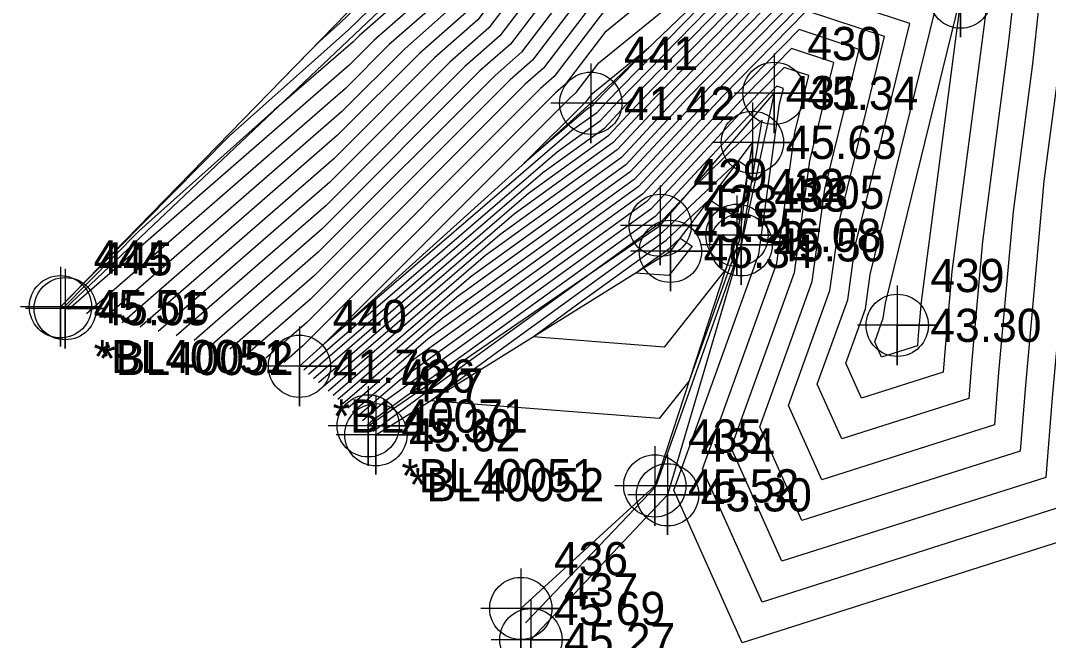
# Model space of a CAD drawing. Extents: x 2090860 to 2091277, y 159470 to 160080.
# Drawn here: x 2090967.2 to 2091044.6, y 159683.4 to 159730.1 of the extents above; entities that cross this region are included whole.
import ezdxf

# ---------------------------------------------------------------- set-up
doc = ezdxf.new("R2010")
doc.units = 0
for name, color, linetype in [('DTM Contours Major', 7, 'Continuous'), ('DTM Contours Minor', 7, 'Continuous'), ('Exist DTM Breakline', 7, 'Continuous'), ('Exist DTM Breakline Cogo Comment', 7, 'Continuous'), ('Exist DTM Breakline Cogo Elevation', 7, 'Continuous'), ('Exist DTM Breakline Cogo Number', 7, 'Continuous'), ('Exist DTM Breakline Cogo Point CELL', 7, 'Continuous'), ('Exist DTM Breakline Underwater', 7, 'Continuous'), ('Exist DTM Breakline Underwater Cogo Comment', 7, 'Continuous'), ('Exist DTM Breakline Underwater Cogo Elevation', 7, 'Continuous'), ('Exist DTM Breakline Underwater Cogo Number', 7, 'Continuous'), ('Exist DTM Breakline Underwater Cogo Point CELL', 7, 'Continuous'), ('Exist DTM Regular Point Underwater CELL', 7, 'Continuous'), ('Exist DTM Regular Point Underwater Cogo Elevation', 7, 'Continuous'), ('Exist DTM Regular Point Underwater Cogo Number', 7, 'Continuous')]:
    doc.layers.add(name, color=color, linetype=linetype)

msp = doc.modelspace()

# ---------------------------------------------------------------- linework, layer by layer
at = {"layer": 'DTM Contours Major'}
for points in [[(2091091.582, 159898.637), (2091075.464, 159895.754), (2091071.361, 159891.649), (2091065.515, 159864.769), (2091059.162, 159855.905), (2091062.527, 159845.344), (2091062.382, 159844.528), (2091071.24, 159827.424), (2091068.468, 159817.052), (2091062.553, 159811.484), (2091060.259, 159801.479), (2091046.876, 159791.945), (2091037.586, 159782.801), (2091031.987, 159764.384), (2091026.688, 159760.214), (2091021.294, 159752.688), (2091014.874, 159747.469), (2091001.671, 159730.125), (2090998.416, 159727.263), (2090990.823, 159719.668), (2090976.25, 159706.989)], [(2091099.517, 159890.851), (2091094.379, 159889.932), (2091085.334, 159880.882), (2091082.516, 159867.927), (2091070.303, 159850.886), (2091072.441, 159844.175), (2091072.201, 159842.82), (2091077.78, 159832.047), (2091073.12, 159814.614), (2091069.924, 159811.606), (2091065.116, 159790.633), (2091059.844, 159786.877), (2091043.696, 159770.983), (2091041.123, 159762.521), (2091029.056, 159753.026), (2091026.145, 159748.964), (2091013.055, 159738.321), (2091004.963, 159727.692), (2091002.968, 159725.938), (2090989.66, 159712.626), (2090981.654, 159705.661)], [(2091031.476, 159794.619), (2091026.533, 159778.36), (2091022.159, 159773.459), (2091024.771, 159765.861), (2091016.801, 159756.497), (2091016.608, 159756.29), (2091015.762, 159755.383), (2091014.915, 159754.282), (2090998.378, 159732.557), (2090993.863, 159728.588), (2090991.986, 159726.71), (2090970.846, 159708.318)], [(2091087.501, 159783.333), (2091087.769, 159779.288), (2091084.366, 159766.629), (2091076.14, 159769.26), (2091074.973, 159768.174), (2091066.061, 159756.411), (2091053.904, 159745.604), (2091047.888, 159738.533), (2091043.463, 159732.701), (2091041.966, 159731.422), (2091041.639, 159728.479), (2091039.685, 159713.437), (2091038.871, 159704.507), (2091038.64, 159701.617), (2091029.076, 159698.576), (2091027.234, 159702.684), (2091029.528, 159709.044), (2091030.086, 159713.086), (2091034.203, 159729.856), (2091026.977, 159732.23), (2091019.254, 159724.332), (2091013.442, 159718.102), (2090999.017, 159707.674), (2090991.506, 159701.21)], [(2091075.953, 159781.891), (2091074.613, 159776.904), (2091071.372, 159777.941), (2091070.912, 159777.513), (2091056.779, 159758.858), (2091051.193, 159753.892), (2091040.5, 159741.323), (2091036.181, 159735.631), (2091029.212, 159737.921), (2091015.739, 159724.142), (2091012.177, 159720.324), (2091003.337, 159713.933), (2090990.035, 159702.486)], [(2090988.564, 159703.762), (2091007.657, 159720.192), (2091010.912, 159722.546), (2091012.224, 159723.952), (2091031.448, 159743.611), (2091032.475, 159743.273), (2091033.111, 159744.112), (2091040.966, 159753.345), (2091031.424, 159745.838), (2091030.995, 159745.239), (2091011.235, 159729.174), (2091008.255, 159725.259), (2091007.521, 159724.613), (2090988.497, 159705.583), (2090987.059, 159704.332)], [(2091046.379, 159693.703), (2091023.075, 159686.293), (2091018.587, 159696.304), (2091024.177, 159711.802), (2091025.536, 159721.65), (2091026.587, 159725.933), (2091024.742, 159726.54), (2091022.769, 159724.523), (2091014.707, 159715.88), (2090994.697, 159701.415), (2090992.977, 159699.935)], [(2091008.827, 159708.454), (2091015.844, 159713.532), (2091019.111, 159716.597), (2091021.386, 159715.096), (2091021.229, 159713.807), (2091020.35, 159711.347), (2091015.693, 159705.481), (2091005.827, 159706.251), (2091008.827, 159708.454)]]:
    msp.add_lwpolyline(points, dxfattribs=at)
at = {"layer": 'DTM Contours Minor'}
for points in [[(2091085.63, 159904.476), (2091061.277, 159900.12), (2091060.882, 159899.725), (2091052.763, 159862.4), (2091050.806, 159859.669), (2091055.091, 159846.22), (2091055.018, 159845.809), (2091066.336, 159823.957), (2091064.979, 159818.88), (2091057.025, 159811.393), (2091056.616, 159809.613), (2091037.15, 159795.745), (2091033.004, 159791.665), (2091025.134, 159765.782), (2091024.911, 159765.606), (2091017.656, 159755.482), (2091016.238, 159754.329), (2090999.201, 159731.949), (2090995.001, 159728.257), (2090991.695, 159724.95), (2090972.197, 159707.986)], [(2091087.614, 159902.53), (2091066.006, 159898.665), (2091064.375, 159897.033), (2091057.014, 159863.189), (2091053.591, 159858.414), (2091057.57, 159845.928), (2091057.473, 159845.382), (2091067.971, 159825.113), (2091066.142, 159818.271), (2091058.867, 159811.424), (2091057.831, 159806.902), (2091040.392, 159794.478), (2091034.531, 159788.71), (2091027.419, 159765.316), (2091025.503, 159763.809), (2091018.868, 159754.551), (2091015.783, 159752.042), (2091000.024, 159731.341), (2090996.139, 159727.925), (2090991.404, 159723.189), (2090973.548, 159707.654)], [(2091089.598, 159900.583), (2091070.735, 159897.209), (2091067.868, 159894.341), (2091061.264, 159863.979), (2091056.377, 159857.16), (2091060.048, 159845.636), (2091059.927, 159844.955), (2091069.606, 159826.269), (2091067.305, 159817.661), (2091060.71, 159811.454), (2091059.045, 159804.19), (2091043.634, 159793.212), (2091036.059, 159785.755), (2091029.703, 159764.85), (2091026.095, 159762.012), (2091020.081, 159753.62), (2091015.328, 159749.755), (2091000.847, 159730.733), (2090997.277, 159727.594), (2090991.114, 159721.429), (2090974.899, 159707.322)], [(2091093.566, 159896.69), (2091080.192, 159894.298), (2091074.854, 159888.957), (2091069.765, 159865.558), (2091061.947, 159854.65), (2091065.005, 159845.052), (2091064.837, 159844.101), (2091072.875, 159828.58), (2091069.631, 159816.443), (2091064.396, 159811.515), (2091061.473, 159798.767), (2091050.118, 159790.678), (2091039.113, 159779.846), (2091034.271, 159763.918), (2091027.28, 159758.417), (2091022.507, 159751.757), (2091014.419, 159745.182), (2091002.494, 159729.516), (2090999.554, 159726.932), (2090990.532, 159717.907), (2090977.601, 159706.657)], [(2091095.549, 159894.744), (2091084.921, 159892.843), (2091078.348, 159886.266), (2091074.015, 159866.348), (2091064.733, 159853.396), (2091067.484, 159844.76), (2091067.291, 159843.674), (2091074.51, 159829.736), (2091070.794, 159815.833), (2091066.238, 159811.545), (2091062.688, 159796.056), (2091053.36, 159789.411), (2091040.641, 159776.892), (2091036.555, 159763.452), (2091027.872, 159756.62), (2091023.719, 159750.826), (2091013.964, 159742.895), (2091003.317, 159728.908), (2091000.692, 159726.601), (2090990.241, 159716.147), (2090978.952, 159706.325)], [(2091097.533, 159892.797), (2091089.65, 159891.387), (2091081.841, 159883.574), (2091078.266, 159867.137), (2091067.518, 159852.141), (2091069.963, 159844.468), (2091069.746, 159843.247), (2091076.145, 159830.892), (2091071.957, 159815.224), (2091068.081, 159811.575), (2091063.902, 159793.344), (2091056.602, 159788.144), (2091042.168, 159773.937), (2091038.839, 159762.987), (2091028.464, 159754.823), (2091024.932, 159749.895), (2091013.509, 159740.608), (2091004.14, 159728.3), (2091001.83, 159726.269), (2090989.951, 159714.386), (2090980.303, 159705.993)], [(2091101.501, 159888.904), (2091099.107, 159888.476), (2091088.827, 159878.19), (2091086.766, 159868.717), (2091073.088, 159849.632), (2091074.92, 159843.883), (2091074.655, 159842.393), (2091079.415, 159833.203), (2091074.283, 159814.005), (2091071.767, 159811.636), (2091066.33, 159787.921), (2091063.086, 159785.61), (2091045.223, 159768.028), (2091043.407, 159762.055), (2091029.648, 159751.229), (2091027.357, 159748.032), (2091012.6, 159736.034), (2091005.786, 159727.084), (2091004.106, 159725.607), (2090989.369, 159710.865), (2090983.005, 159705.329)], [(2091017.431, 159786.838), (2091024.63, 159765.903), (2091019.161, 159759.478), (2091016.387, 159756.502), (2091004.237, 159743.466), (2090996.79, 159733.786), (2090993.454, 159730.838), (2090991.938, 159729.378), (2090982.952, 159721.358), (2090970.247, 159708.52)], [(2091066.328, 159784.343), (2091046.751, 159765.073), (2091045.691, 159761.589), (2091030.24, 159749.432), (2091028.57, 159747.101), (2091012.145, 159733.748), (2091006.609, 159726.476), (2091005.244, 159725.276), (2090989.078, 159709.104), (2090984.356, 159704.996)], [(2091090.414, 159783.295), (2091090.724, 159778.637), (2091086.804, 159764.06), (2091077.332, 159767.09), (2091075.988, 159765.839), (2091068.382, 159755.8), (2091054.582, 159743.532), (2091049.736, 159737.835), (2091046.17, 159733.137), (2091043.929, 159731.221), (2091043.438, 159726.812), (2091041.995, 159715.704), (2091040.889, 159703.567), (2091040.574, 159699.638), (2091027.576, 159695.505), (2091025.072, 159701.089), (2091028.191, 159709.733), (2091028.948, 159715.227), (2091032.299, 159728.875), (2091026.418, 159730.808), (2091020.133, 159724.38), (2091013.758, 159717.546), (2090997.937, 159706.109), (2090991.874, 159700.892)], [(2091093.328, 159783.257), (2091093.678, 159777.986), (2091089.243, 159761.491), (2091078.524, 159764.92), (2091077.003, 159763.504), (2091070.702, 159755.188), (2091055.259, 159741.46), (2091051.583, 159737.138), (2091048.878, 159733.573), (2091045.891, 159731.02), (2091045.237, 159725.146), (2091044.305, 159717.971), (2091042.908, 159702.627), (2091042.509, 159697.66), (2091026.075, 159692.434), (2091022.911, 159699.494), (2091026.853, 159710.423), (2091027.811, 159717.368), (2091030.395, 159727.895), (2091025.859, 159729.385), (2091021.012, 159724.428), (2091014.074, 159716.991), (2090996.857, 159704.544), (2090992.242, 159700.573)], [(2091096.241, 159783.219), (2091096.632, 159777.335), (2091091.681, 159758.923), (2091079.716, 159762.75), (2091078.018, 159761.17), (2091073.023, 159754.576), (2091055.937, 159739.388), (2091053.43, 159736.44), (2091051.585, 159734.01), (2091047.854, 159730.819), (2091047.036, 159723.479), (2091046.615, 159720.238), (2091044.926, 159701.687), (2091044.444, 159695.681), (2091024.575, 159689.363), (2091020.749, 159697.899), (2091025.515, 159711.112), (2091026.673, 159719.509), (2091028.491, 159726.914), (2091025.301, 159727.962), (2091021.891, 159724.475), (2091014.39, 159716.435), (2090995.777, 159702.98), (2090992.609, 159700.254)], [(2091019.078, 159782.234), (2091024.701, 159765.882), (2091017.981, 159757.987), (2091016.497, 159756.396), (2091010, 159749.425), (2091003.491, 159740.964), (2090997.555, 159733.165), (2090992.725, 159728.919), (2090992.277, 159728.471), (2090986.347, 159723.312), (2090976.167, 159714.226), (2090970.443, 159708.442)], [(2090987.359, 159726.086), (2090989.738, 159728.489), (2090991.312, 159729.894), (2090995.036, 159733.482), (2090996.1, 159734.422), (2090998.474, 159737.508), (2091016.276, 159756.608), (2091020.341, 159760.969), (2091024.559, 159765.924), (2091019.007, 159782.07)], [(2090989.3, 159703.124), (2091005.497, 159717.062), (2091011.545, 159721.435), (2091013.982, 159724.047), (2091030.33, 159740.766), (2091034.328, 159739.452), (2091036.806, 159742.718), (2091049.838, 159758.036), (2091052.138, 159760.081), (2091068.882, 159782.182)], [(2091078.907, 159781.24), (2091077.051, 159774.335), (2091072.564, 159775.771), (2091071.927, 159775.178), (2091059.099, 159758.246), (2091051.871, 159751.82), (2091042.347, 159740.625), (2091037.107, 159733.72), (2091028.653, 159736.498), (2091016.618, 159724.19), (2091012.493, 159719.768), (2091002.257, 159712.368), (2090990.403, 159702.167)], [(2091081.861, 159780.589), (2091079.489, 159771.767), (2091073.756, 159773.601), (2091072.942, 159772.843), (2091061.42, 159757.634), (2091052.549, 159749.748), (2091044.194, 159739.928), (2091038.048, 159731.828), (2091038.042, 159731.823), (2091038.04, 159731.812), (2091035.064, 159708.902), (2091034.835, 159706.388), (2091034.77, 159705.574), (2091032.077, 159704.717), (2091031.558, 159705.874), (2091032.204, 159707.665), (2091032.361, 159708.804), (2091038.011, 159731.817), (2091028.095, 159735.075), (2091017.497, 159724.237), (2091012.809, 159719.213), (2091001.177, 159710.803), (2090990.771, 159701.848)], [(2091069.897, 159779.847), (2091054.458, 159759.469), (2091050.515, 159755.964), (2091038.653, 159742.02), (2091035.254, 159737.542), (2091029.771, 159739.343), (2091014.861, 159724.095), (2091011.861, 159720.879), (2091004.417, 159715.498), (2090989.667, 159702.805)], [(2091084.815, 159779.939), (2091081.928, 159769.198), (2091074.948, 159771.43), (2091073.958, 159770.509), (2091063.74, 159757.023), (2091053.226, 159747.676), (2091046.041, 159739.23), (2091040.755, 159732.265), (2091040.004, 159731.622), (2091039.84, 159730.145), (2091037.374, 159711.17), (2091036.853, 159705.448), (2091036.705, 159703.595), (2091030.576, 159701.647), (2091029.396, 159704.279), (2091030.866, 159708.355), (2091031.224, 159710.945), (2091036.107, 159730.837), (2091027.536, 159733.653), (2091018.376, 159724.285), (2091013.126, 159718.657), (2091000.097, 159709.239), (2090991.138, 159701.529)], [(2090988.932, 159703.443), (2091006.577, 159718.627), (2091011.229, 159721.99), (2091013.103, 159723.999), (2091030.889, 159742.188), (2091033.401, 159741.363), (2091034.959, 159743.415), (2091049.16, 159760.108), (2091049.817, 159760.692), (2091058.581, 159772.26), (2091048.278, 159762.119), (2091047.975, 159761.123), (2091030.832, 159747.635), (2091029.783, 159746.17), (2091011.69, 159731.461), (2091007.432, 159725.867), (2091006.383, 159724.945), (2090988.787, 159707.344), (2090985.707, 159704.664)], [(2090990.11, 159705.727), (2091008.659, 159724.282), (2091009.079, 159724.651), (2091010.781, 159726.887), (2091027.762, 159740.693), (2091011.346, 159723.904), (2091010.596, 159723.101), (2091008.736, 159721.757), (2090990.11, 159705.727)], [(2091005.174, 159719.326), (2091009.797, 159723.951), (2091009.902, 159724.043), (2091010.326, 159724.6), (2091014.559, 159728.041), (2091010.467, 159723.857), (2091010.28, 159723.657), (2091009.816, 159723.322), (2091005.174, 159719.326)], [(2091048.314, 159691.724), (2091021.574, 159683.222), (2091016.425, 159694.709), (2091022.839, 159712.491), (2091024.398, 159723.792), (2091024.683, 159724.953), (2091024.183, 159725.117), (2091023.648, 159724.57), (2091015.023, 159715.324), (2090993.617, 159699.85), (2090993.345, 159699.616)], [(2091005.255, 159684.74), (2091010.318, 159689.997), (2091015.068, 159694.991), (2091021.468, 159713.087), (2091021.501, 159713.18), (2091021.512, 159713.255), (2091023.088, 159722.575), (2091017.569, 159717.159), (2091015.339, 159714.769), (2091010.853, 159711.526), (2090997.865, 159702.125), (2090993.785, 159699.13)], [(2091003.346, 159705.29), (2091015.599, 159714.158), (2091021.305, 159719.509), (2091022.038, 159719.025), (2091021.363, 159713.494), (2091017.592, 159702.941), (2091015.336, 159700.099), (2090998.106, 159701.442), (2091003.346, 159705.29)], [(2091014.308, 159711.618), (2091016.089, 159712.907), (2091016.918, 159713.684), (2091017.818, 159713.09), (2091016.051, 159710.864), (2091013.547, 159711.059), (2091014.308, 159711.618)]]:
    msp.add_lwpolyline(points, dxfattribs=at)
at = {"layer": 'Exist DTM Breakline'}
for points in [[(2090970.238, 159708.524), (2090995.777, 159734.72), (2091024.32, 159765.995), (2091015.838, 159787.603), (2090997.039, 159829.071)], [(2090970.603, 159708.378), (2090997.094, 159733.506), (2091024.833, 159765.843), (2091016.946, 159788.306), (2090998.355, 159829.241)], [(2090993.414, 159699.556), (2091015.406, 159714.651), (2091023.975, 159724.588), (2091021.496, 159713.183), (2091015.958, 159694.364), (2091005.671, 159683.46)], [(2090993.999, 159698.884), (2091016.172, 159712.694), (2091022.349, 159720.896), (2091021.188, 159713.902), (2091015, 159695.039), (2091004.908, 159685.809)]]:
    msp.add_lwpolyline(points, dxfattribs=at)
at = {"layer": 'Exist DTM Breakline Cogo Point CELL'}
for points in [[(2091023.975, 159727.588), (2091023.975, 159721.588), (2091023.975, 159724.588), (2091026.975, 159724.588), (2091020.975, 159724.588)], [(2091022.349, 159723.896), (2091022.349, 159717.896), (2091022.349, 159720.896), (2091025.349, 159720.896), (2091019.349, 159720.896)], [(2091015.406, 159717.651), (2091015.406, 159711.651), (2091015.406, 159714.651), (2091018.406, 159714.651), (2091012.406, 159714.651)], [(2091021.188, 159716.902), (2091021.188, 159710.902), (2091021.188, 159713.902), (2091024.188, 159713.902), (2091018.188, 159713.902)], [(2091021.496, 159716.183), (2091021.496, 159710.183), (2091021.496, 159713.183), (2091024.496, 159713.183), (2091018.496, 159713.183)], [(2091016.172, 159715.694), (2091016.172, 159709.694), (2091016.172, 159712.694), (2091019.172, 159712.694), (2091013.172, 159712.694)], [(2090970.238, 159711.524), (2090970.238, 159705.524), (2090970.238, 159708.524), (2090973.238, 159708.524), (2090967.238, 159708.524)], [(2090970.603, 159711.378), (2090970.603, 159705.378), (2090970.603, 159708.378), (2090973.603, 159708.378), (2090967.603, 159708.378)], [(2090993.414, 159702.556), (2090993.414, 159696.556), (2090993.414, 159699.556), (2090996.414, 159699.556), (2090990.414, 159699.556)], [(2090993.999, 159701.884), (2090993.999, 159695.884), (2090993.999, 159698.884), (2090996.999, 159698.884), (2090990.999, 159698.884)], [(2091015, 159698.039), (2091015, 159692.039), (2091015, 159695.039), (2091018, 159695.039), (2091012, 159695.039)], [(2091015.958, 159697.364), (2091015.958, 159691.364), (2091015.958, 159694.364), (2091018.958, 159694.364), (2091012.958, 159694.364)], [(2091004.908, 159688.809), (2091004.908, 159682.809), (2091004.908, 159685.809), (2091007.908, 159685.809), (2091001.908, 159685.809)], [(2091005.671, 159686.46), (2091005.671, 159680.46), (2091005.671, 159683.46), (2091008.671, 159683.46), (2091002.671, 159683.46)]]:
    msp.add_lwpolyline(points, dxfattribs=at)
for centre in [(2091023.975, 159724.588), (2091022.349, 159720.896), (2091015.406, 159714.651), (2091021.188, 159713.902), (2091021.496, 159713.183), (2091016.172, 159712.694), (2090970.238, 159708.524), (2090970.603, 159708.378), (2090993.414, 159699.556), (2090993.999, 159698.884), (2091015, 159695.039), (2091015.958, 159694.364), (2091004.908, 159685.809), (2091005.671, 159683.46)]:
    msp.add_circle(centre, 2.344, dxfattribs=at)
at = {"layer": 'Exist DTM Breakline Underwater'}
msp.add_lwpolyline([(2090988.242, 159704.041), (2091010.175, 159723.841), (2091048.889, 159760.937), (2091068.273, 159783.583), (2091089.722, 159842.139), (2091103.231, 159887.207)], dxfattribs=at)
at = {"layer": 'Exist DTM Breakline Underwater Cogo Point CELL'}
for points in [[(2091010.175, 159726.841), (2091010.175, 159720.841), (2091010.175, 159723.841), (2091013.175, 159723.841), (2091007.175, 159723.841)], [(2090988.242, 159707.041), (2090988.242, 159701.041), (2090988.242, 159704.041), (2090991.242, 159704.041), (2090985.242, 159704.041)]]:
    msp.add_lwpolyline(points, dxfattribs=at)
for centre in [(2091010.175, 159723.841), (2090988.242, 159704.041)]:
    msp.add_circle(centre, 2.344, dxfattribs=at)
at = {"layer": 'Exist DTM Regular Point Underwater CELL'}
for points in [[(2091038.026, 159734.825), (2091038.026, 159728.825), (2091038.026, 159731.825), (2091041.026, 159731.825), (2091035.026, 159731.825)], [(2091033.253, 159710.125), (2091033.253, 159704.125), (2091033.253, 159707.125), (2091036.253, 159707.125), (2091030.253, 159707.125)]]:
    msp.add_lwpolyline(points, dxfattribs=at)
for centre in [(2091038.026, 159731.825), (2091033.253, 159707.125)]:
    msp.add_circle(centre, 2.344, dxfattribs=at)

# ---------------------------------------------------------------- texts
at = {"layer": 'Exist DTM Breakline Cogo Comment'}
for s, p in [('4005', (2091024.849, 159715.896)), ('*BL40051', (2090972.738, 159703.524)), ('*BL40052', (2090973.103, 159703.378)), ('*BL40051', (2090995.914, 159694.556)), ('*BL40052', (2090996.499, 159693.884))]:
    msp.add_text(s, height=2.5, dxfattribs=at).set_placement(p)
at = {"layer": 'Exist DTM Breakline Cogo Elevation'}
for s, p in [('45.34', (2091026.475, 159723.338)), ('45.63', (2091024.849, 159719.646)), ('45.55', (2091017.906, 159713.401)), ('46.08', (2091023.688, 159712.652)), ('46.34', (2091018.672, 159711.444)), ('45.50', (2091023.996, 159711.933)), ('45.51', (2090972.738, 159707.274)), ('45.05', (2090973.103, 159707.128)), ('45.30', (2090995.914, 159698.306)), ('45.62', (2090996.499, 159697.634)), ('45.52', (2091017.5, 159693.789)), ('45.30', (2091018.458, 159693.114)), ('45.69', (2091007.408, 159684.559)), ('45.27', (2091008.171, 159682.21))]:
    msp.add_text(s, height=2.5, dxfattribs=at).set_placement(p)
at = {"layer": 'Exist DTM Breakline Cogo Number'}
for s, p in [('430', (2091026.475, 159727.088)), ('431', (2091024.849, 159723.396)), ('429', (2091017.906, 159717.151)), ('432', (2091023.688, 159716.402)), ('428', (2091018.672, 159715.194)), ('433', (2091023.996, 159715.683)), ('444', (2090972.738, 159711.024)), ('445', (2090973.103, 159710.878)), ('426', (2090995.914, 159702.056)), ('427', (2090996.499, 159701.384)), ('435', (2091017.5, 159697.539)), ('434', (2091018.458, 159696.864)), ('436', (2091007.408, 159688.309)), ('437', (2091008.171, 159685.96))]:
    msp.add_text(s, height=2.5, dxfattribs=at).set_placement(p)
at = {"layer": 'Exist DTM Breakline Underwater Cogo Comment'}
msp.add_text('*BL40071', height=2.5, dxfattribs=at).set_placement((2090990.742, 159699.041))
at = {"layer": 'Exist DTM Breakline Underwater Cogo Elevation'}
for s, p in [('41.42', (2091012.675, 159722.591)), ('41.78', (2090990.742, 159702.791))]:
    msp.add_text(s, height=2.5, dxfattribs=at).set_placement(p)
at = {"layer": 'Exist DTM Breakline Underwater Cogo Number'}
for s, p in [('441', (2091012.675, 159726.341)), ('440', (2090990.742, 159706.541))]:
    msp.add_text(s, height=2.5, dxfattribs=at).set_placement(p)
at = {"layer": 'Exist DTM Regular Point Underwater Cogo Elevation'}
msp.add_text('43.30', height=2.5, dxfattribs=at).set_placement((2091035.753, 159705.875))
at = {"layer": 'Exist DTM Regular Point Underwater Cogo Number'}
msp.add_text('439', height=2.5, dxfattribs=at).set_placement((2091035.753, 159709.625))

doc.saveas('drawing.dxf')
